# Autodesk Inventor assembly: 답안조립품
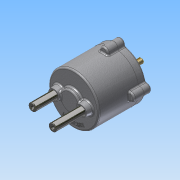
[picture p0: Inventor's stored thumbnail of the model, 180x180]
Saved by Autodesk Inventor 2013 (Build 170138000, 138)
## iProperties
Created: 2015-02
Part Number: 답안조립품
Document SubType Name: Assembly
Designer: WINDOWS7
Mass: 1967.31 g
Surface Area: 1692.74 cm^2
Volume: 412.889 cm^3
Density: 4.76474 g/cm^3
Author: WINDOWS7
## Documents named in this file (13)
- C:\Users\WINDOWS7\Desktop\350208V1009\답안조립품.iam
- C:\Users\WINDOWS7\Desktop\350208V1009\몸체.ipt
- C:\Users\WINDOWS7\Desktop\350208V1009\커버.ipt
- C:\Users\WINDOWS7\Desktop\350208V1009\베어링 NA 4900.ipt
- C:\Users\WINDOWS7\Desktop\350208V1009\오일실.ipt
- C:\Users\WINDOWS7\Desktop\350208V1009\M5x0.5x20.ipt
- C:\Users\WINDOWS7\Desktop\350208V1009\메인 축.ipt
- C:\Users\WINDOWS7\Desktop\350208V1009\멈춤링 22 x 1.2.ipt
- C:\Users\WINDOWS7\Desktop\350208V1009\멈춤링 10 x 1.ipt
- C:\Users\WINDOWS7\Desktop\350208V1009\판캠.ipt
- C:\Users\WINDOWS7\Desktop\350208V1009\슬라이드 축.ipt
- C:\Users\WINDOWS7\Desktop\350208V1009\가변스프링1.ipt
- C:\Users\WINDOWS7\Desktop\350208V1009\가변스프링2.ipt
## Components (6 placed, 3 different names)
1. 가변스프링1:1
2. 가변스프링2:1
3. M5x0.5x20:1
4. M5x0.5x20:2
5. M5x0.5x20:3
6. M5x0.5x20:4
